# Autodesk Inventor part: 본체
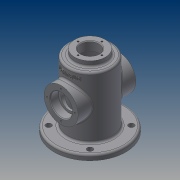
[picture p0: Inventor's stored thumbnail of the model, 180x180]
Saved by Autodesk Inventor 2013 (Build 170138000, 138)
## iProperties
Created: 2014-12
Part Number: 본체
Material: Generic
Document SubType Name: Modeling
Designer: HS002
Density: 1 g/cm^3
Author: HS002
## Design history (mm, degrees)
sketch "스케치1"
  geometry: C1 r 32.5 at (0, 0); 1 further point
  constraints: 1 centre point, 1 coincident
  dimensions: "d0" = 65 diameter of C1
extrude "돌출1" new body sketch "스케치1" distance "d1" = 98; taper "d2" = 0 deg
fillet "모깎기1" dims "d3" = 3
feature "쉘1" dims "d4" = 5
fillet "모깎기2" dims "d5" = 3
sketch "스케치2"
  geometry: C1 r 29.5 at (0, 0) reference; C2 r 22.5 at (0, 0)
  constraints: 1 centre point, 1 coincident
  dimensions: "d6" = 45 diameter of C2
extrude "돌출2" join sketch "스케치2" distance "d7" = 8; taper "d8" = 0 deg
sketch "스케치3"
  geometry: C1 r 22.5 at (0, 0) reference; C2 r 13.5 at (0, 0)
  constraints: 1 centre point, 1 coincident
  dimensions: "d9" = 27 diameter of C2
extrude "돌출3" cut sketch "스케치3" distance "d10" = 111; taper "d11" = 0 deg
sketch "스케치4" dims "d12" = 35
  geometry: C1 r 22.5 at (0, 0) reference; C2 r 31.231 at (0, 17.5); 1 further point
  constraints: 1 centre point, 1 coincident, 1 vertical alignment, 2 other
hole "구멍1" sketch "스케치4" at (0, 17.5) diameter "d13" = 2.459; stored, may be unused: countersink angle "d17" = 90 deg, drill point angle "d19" = 118 deg; dims "d14" = 6, "d15" = 4, "d16" = 2, "d18" = 8
node "작업 평면1"
sketch "스케치5"
  geometry: C1 r 25 at (0, 55); 1 further point
  constraints: 1 centre point
  dimensions: "d24" = 50 diameter of C1; "d25" = 55 distance of C1.centre point (0, 0)
extrude "돌출4" join sketch "스케치5" stored distance "d26" = 111; taper "d27" = 0 deg
hole "구멍2" diameter "d30" = 25; stored, may be unused: countersink angle "d34" = 90 deg, drill point angle "d36" = 118 deg; dims "d28" = 10, "d29" = 10, "d31" = 6, "d32" = 32, "d33" = 12, "d35" = 42.5
sketch "스케치6" dims "d37" = 41
  geometry: C1 r 25 at (0, 0) reference; C2 r 9.403 at (-20.5, 0); 2 further points
  constraints: 1 centre point, 1 coincident, 1 horizontal alignment, 2 other
hole "구멍3" sketch "스케치6" at (-20.5, 0) diameter "d38" = 2.459; stored, may be unused: countersink angle "d42" = 90 deg, drill point angle "d44" = 118 deg; dims "d39" = 6, "d40" = 32, "d41" = 12, "d43" = 8
fillet "모깎기3" dims "d48" = 0.3
chamfer "모따기1" distance "d49" = 1; stored, may be unused: second distance "d50" = 2, angle "d51" = 45 deg
sketch "스케치7"
  geometry: C1 r 27.5 at (0, 0) reference; C2 r 32.5 at (0, 0) reference; C3 r 52.5 at (0, 0)
  constraints: 1 centre point, 1 coincident
  dimensions: "d52" = 105 diameter of C3
extrude "돌출5" join sketch "스케치7" distance "d53" = 8; taper "d54" = 0 deg
fillet "모깎기4" dims "d55" = 3
sketch "스케치8"
  geometry: L1 (0, 0)-(43, 0); L2 (0, 0)-(30.406, 30.406); C1 r 35.5 at (0, 0) reference; C2 r 4 at (30.406, 30.406); A1 r 43 centre (0, 0) between (43, 0) and (30.406, 30.406)
  constraints: 4 end point, 2 centre point, 2 coincident, 2 point on circle, 1 horizontal
  dimensions: "d56" = 86 diameter of A1; "d57" = 45 deg angle of L2 L1; "d59" = 8 diameter of C2
extrude "돌출6" cut sketch "스케치8" distance "d60" = 8; taper "d61" = 0 deg
node "작업 평면2"
sketch "스케치9"
  geometry: L1 (-29.5, 98)-(29.5, 98) reference; 3 further points
  constraints: 1 midpoint, 1 vertical alignment, 1 other
  dimensions: "d66" = 9 distance from line of L1 point (0, 89)
feature "엠보싱1" sketch "스케치9" dims "d67" = 1, "d68" = 0
node "솔리드1"
pattern_circular "원형 패턴1" dims angle "d21" = 360 deg
pattern_circular "원형 패턴2" dims angle "d46" = 360 deg
mirror "대칭1"
pattern_circular "원형 패턴3" dims angle "d63" = 360 deg
other parameters: "d23" = 42.5, "d65" = -32.5
